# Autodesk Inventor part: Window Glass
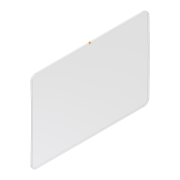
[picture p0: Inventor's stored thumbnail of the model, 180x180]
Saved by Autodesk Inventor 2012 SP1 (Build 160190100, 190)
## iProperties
Created: 2006-09
Part Number: Window Glass
Material: Glass
Document SubType Name: Modeling
Mass: 2664.51 g
Surface Area: 3610.24 cm^2
Volume: 1222.25 cm^3
Density: 2.18 g/cm^3
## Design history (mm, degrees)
sketch "Sketch2"
  geometry: L1 (-4.142, 0)-(0.502, 0) reference; L2 (0, -39.201)-(0, 460.6) reference; 3 further points
  constraints: 1 point on line, 3 other
  dimensions: "d2" = 200 distance from line of point (-3, 200) L1; "d3" = 350 distance from line of point (0, 350) L1; "d6" = 3 distance from line of point (-3, 200) L2
sketch "Sketch3"
  geometry: L1 (-3.5, 250)-(3.5, 250); L2 (3.5, 250)-(3.5, -250); L3 (3.5, -250)-(-3.5, -250); L4 (-3.5, -250)-(-3.5, 250); L5 (-3.5, 250)-(3.5, -250); 2 further points
  constraints: 10 end point, 2 parallel, 1 coincident, 1 horizontal, 1 midpoint, 1 perpendicular
  dimensions: "d0" = 500 distance of L1.end L2.end; "d1" = 7 distance of L1.start L1.end
sweep "Sweep1" sketch "Sketch2", "Sketch3" dims "d4" = 0
fillet "Fillet1" dims "d5" = 20
workpoint "Work Point2"
body "Solid1"
